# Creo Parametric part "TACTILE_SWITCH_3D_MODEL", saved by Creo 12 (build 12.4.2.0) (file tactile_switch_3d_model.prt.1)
Units: Custom; MM, KILOGRAM, SECS

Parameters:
  PTC_WM_ITERATION = "0"
  PTC_WM_VERSION = "-.0"
  PTC_WM_LIFECYCLE_STATE = "In Work"
  PTC_WM_LIFECYCLE = "MO_CADDocument"
  PTC_WM_CREATED_BY = "Maximilian Roepper (Z0017RMS: MO)"
  PTC_WM_CREATED_ON = "18-Sep-26 11:36:42 AM"
  PTC_WM_MODIFIED_BY = "Maximilian Roepper (Z0017RMS: MO)"
  PTC_WM_MODIFIED_ON = "18-Sep-26 11:36:46 AM"
  PDMLINKNUMBER = "PDM000071455109"
  PTC_WM_NAME = "tactile_switch_3d_model.prt"
  PTC_WM_NUMBER = "PDM000071455109"

Other parameters: WEIGHT, WEIGHT_FACTOR, WEIGHT_ADD, _MASS_TEMP, _DIFF_TEMP, MC_ERRORS, SUPPLIER

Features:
  1. coordinate system
  2. datum plane "PRT_YZ"
  3. datum plane "PRT_XY"
  4. datum plane "PRT_XZ"
  5. coordinate system
  6. datum axis
  7. datum axis
  8. datum axis
  9. coordinate system
  10. imported feature

Other named items: PRT, SIEMENS_MO, DRW_VIEW_ORG, PRT_X, PRT_Y, PRT_Z, CS0, ROUGH_GROB

Layers: 00_STD_CSYS-KSYS, 01_STD_PLANES-EBENEN, 02_STD_AXES-ACHSEN, 03_STD_CSYS-KSYS, 24_IMPORT_FEAT-IMPORT_KE, INTFCLR_5, NONE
